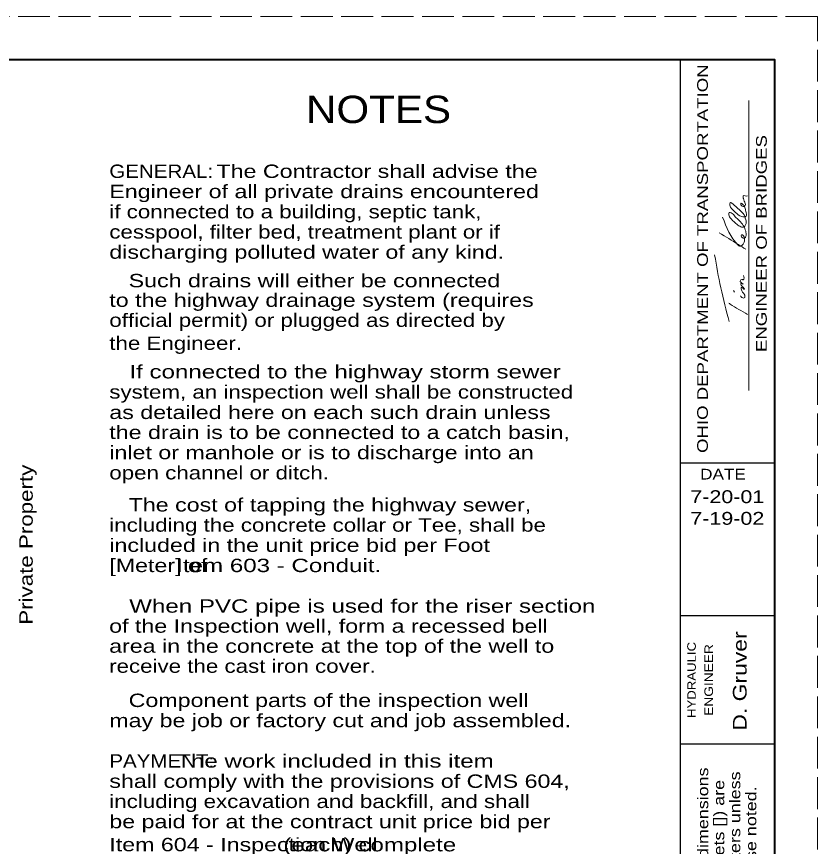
# Model space of a CAD drawing. Extents: x 1083.1 to 1117.1, y 719.4 to 741.4.
# Drawn here: x 1107.77 to 1117.13, y 731.66 to 741.35 of the extents above; entities that cross this region are included whole.
import ezdxf
from ezdxf.enums import TextEntityAlignment as Align

# ---------------------------------------------------------------- set-up
doc = ezdxf.new("R2010")
doc.units = 0
doc.header["$LTSCALE"] = 0.062
doc.linetypes.add('LONG_DASHED', pattern=[7.5, 6, -1.5])
doc.layers.add('1', color=7, linetype='Continuous', lineweight=13)

msp = doc.modelspace()

# ---------------------------------------------------------------- linework, layer by layer
at = {"layer": '1', "lineweight": 25}
for p, q in [((1085.12642, 740.85408), (1116.62642, 740.85408)), ((1115.52642, 719.85408), (1115.52642, 740.85408)), ((1116.62642, 740.85408), (1116.62642, 719.85408)), ((1116.62642, 736.13825), (1115.52642, 736.13825)), ((1116.62642, 734.35408), (1115.52642, 734.35408)), ((1116.62642, 732.85408), (1115.52642, 732.85408))]:
    msp.add_line(p, q, dxfattribs=at)
at = {"layer": '1'}
for p, q in [((1116.32517, 736.98508), (1116.32517, 740.37517)), ((1116.15767, 738.136), (1116.1475, 738.15525))]:
    msp.add_line(p, q, dxfattribs=at)
at = {"layer": '1', "linetype": 'LONG_DASHED'}
msp.add_lwpolyline([(1083.12642, 719.35408), (1117.12642, 719.35408), (1117.12642, 741.35408), (1083.12642, 741.35408)], close=True, dxfattribs=at)
at = {"layer": '1', "lineweight": 40}
msp.add_lwpolyline([(1085.12642, 740.85408), (1116.62642, 740.85408), (1116.62642, 719.85408), (1085.12642, 719.85408)], close=True, dxfattribs=at)
msp.add_lwpolyline([(1085.12642, 740.85408), (1116.62642, 740.85408), (1116.62642, 719.85408), (1085.12642, 719.85408)], close=True, dxfattribs=at)
at = {"layer": '1'}
for points in [[(1116.01825, 739.01108), (1116.20142, 738.68275), (1116.21658, 738.67217), (1116.22675, 738.67217), (1116.25867, 738.69583), (1116.27375, 738.73), (1116.26875, 738.78125), (1116.25183, 738.80308), (1116.23833, 738.80308), (1116.23658, 738.79008), (1116.24675, 738.77492), (1116.26025, 738.7665), (1116.27533, 738.7665), (1116.2905, 738.78808), (1116.29392, 738.80742), (1116.28367, 738.86275), (1116.20142, 738.98317), (1116.15592, 739.02783), (1116.119, 739.06242), (1116.09383, 739.06458), (1116.09558, 739.026), (1116.12075, 738.98725), (1116.188, 738.92492), (1116.23008, 738.8995), (1116.26375, 738.895), (1116.28708, 738.921), (1116.29392, 738.95517), (1116.28883, 738.98092), (1116.25867, 739.05408), (1116.22842, 739.08608), (1116.16783, 739.1395), (1116.13917, 739.16533), (1116.10567, 739.18058), (1116.10225, 739.15258), (1116.11233, 739.12675), (1116.1695, 739.06683), (1116.24017, 739.01958), (1116.29217, 739.02192), (1116.2905, 739.07958), (1116.27867, 739.1225), (1116.26533, 739.14825), (1116.25517, 739.159), (1116.23175, 739.174), (1116.2335, 739.15692), (1116.26875, 739.13542), (1116.28367, 739.14617), (1116.27058, 739.19983), (1116.262, 739.22775), (1116.25867, 739.24042), (1116.25867, 739.25325), (1116.25867, 739.26192), (1116.28367, 739.25975), (1116.30908, 739.25975)], [(1115.97942, 738.82883), (1116.20317, 738.69133), (1116.28883, 738.63567)], [(1116.09567, 737.79183), (1115.997, 738.18708), (1115.92575, 738.56942)], [(1116.22675, 738.09075), (1116.235, 738.08008), (1116.27217, 738.06717), (1116.27692, 738.09958), (1116.25183, 738.136), (1116.23658, 738.17225), (1116.23658, 738.1915), (1116.25183, 738.18525), (1116.262, 738.17442), (1116.27217, 738.17008), (1116.2485, 738.20225), (1116.23658, 738.21725), (1116.2335, 738.23458), (1116.25692, 738.228), (1116.2485, 738.23667), (1116.22333, 738.2645), (1116.2335, 738.27967), (1116.25025, 738.28167), (1116.25867, 738.27967), (1116.26875, 738.301), (1116.262, 738.32892)], [(1116.31083, 737.87625), (1116.10567, 737.99625), (1116.09008, 738.00667)]]:
    msp.add_spline(points, degree=3, dxfattribs=at)

# ---------------------------------------------------------------- texts
for s, height, width, p in [('OHIO DEPARTMENT OF TRANSPORTATION', 0.125, 1.3, (1115.84633, 738.52633)), ('ENGINEER OF BRIDGES', 0.125, 1.3, (1116.53467, 738.70312)), ('Private Property', 0.156, 1.25, (1107.95658, 735.1855)), ('D. Gruver', 0.16, 1.25, (1116.29933, 733.59325)), ('HYDRAULIC', 0.1, 1.15, (1115.7055, 733.60517)), ('ENGINEER', 0.1, 1.2, (1115.90642, 733.60521)), ('All metric dimensions', 0.125, 1.25, (1115.85025, 731.59617)), ('in millimeters unless', 0.125, 1.25, (1116.22525, 731.59621)), ('(in brackets []) are', 0.125, 1.25, (1116.03775, 731.59617)), ('otherwise noted.', 0.125, 1.25, (1116.41275, 731.59617))]:
    msp.add_text(s, height=height, rotation=90, dxfattribs=dict(at, width=width)).set_placement(p, align=Align.CENTER)
for s, height, width, p in [('NOTES', 0.32, 1.15, (1111.15042, 740.11042)), ('GENERAL:', 0.156, 1.15, (1108.85183, 739.46958)), ('   The Contractor shall advise the', 0.156, 1.3, (1109.87783, 739.46958)), ('Engineer of all private drains encountered', 0.156, 1.3, (1108.85183, 739.23358)), ('if connected to a building, septic tank,', 0.156, 1.25, (1108.85183, 738.99758)), ('cesspool, filter bed, treatment plant or if', 0.156, 1.25, (1108.85183, 738.76158)), ('discharging polluted water of any kind.', 0.156, 1.3, (1108.85183, 738.52558)), ('   Such drains will either be connected', 0.156, 1.3, (1108.85183, 738.19242)), ('to the highway drainage system (requires ', 0.156, 1.3, (1108.85183, 737.96367)), ('official permit) or plugged as directed by', 0.156, 1.25, (1108.85183, 737.72967)), ('the Engineer.', 0.156, 1.25, (1108.85183, 737.46125)), ('   If connected to the highway storm sewer', 0.156, 1.35, (1108.85183, 737.12808)), ('system, an inspection well shall be constructed', 0.156, 1.25, (1108.85183, 736.89208)), ('as detailed here on each such drain unless', 0.156, 1.3, (1108.85183, 736.65358)), ('the drain is to be connected to a catch basin,', 0.156, 1.3, (1108.85183, 736.42008)), ('inlet or manhole or is to discharge into an', 0.156, 1.3, (1108.85183, 736.18408)), ('open channel or ditch.', 0.156, 1.25, (1108.85183, 735.94808)), ('   The cost of tapping the highway sewer,', 0.156, 1.3, (1108.85183, 735.57333)), ('including the concrete collar or Tee, shall be', 0.156, 1.25, (1108.85183, 735.33733)), ('included in the unit price bid per Foot', 0.156, 1.3, (1108.85183, 735.10133)), ('[Meter] of', 0.156, 1.3, (1108.85183, 734.86533)), ('          Item 603 - Conduit.', 0.156, 1.35, (1108.85183, 734.86533)), ('   When PVC pipe is used for the riser section ', 0.156, 1.35, (1108.84975, 734.39133)), ('of the Inspection well, form a recessed bell ', 0.156, 1.3, (1108.84975, 734.15733)), ('area in the concrete at the top of the well to ', 0.156, 1.3, (1108.84975, 733.92333)), ('receive the cast iron cover.', 0.156, 1.25, (1108.84975, 733.68933)), ('   Component parts of the inspection well', 0.156, 1.3, (1108.85183, 733.28958)), ('may be job or factory cut and job assembled.', 0.156, 1.3, (1108.85183, 733.05358)), ('PAYMENT:', 0.156, 1.15, (1108.85183, 732.58158)), ('          The work included in this item', 0.156, 1.35, (1108.85183, 732.58158)), ('shall comply with the provisions of CMS 604,', 0.156, 1.3, (1108.85183, 732.34517)), ('including excavation and backfill, and shall', 0.156, 1.25, (1108.85183, 732.10958)), ('be paid for at the contract unit price bid per', 0.156, 1.3, (1108.85183, 731.87358)), ('Item 604 - Inspection Well', 0.156, 1.3, (1108.85183, 731.60467)), ('                          (each) complete', 0.156, 1.35, (1108.85183, 731.60333))]:
    msp.add_text(s, height=height, dxfattribs=dict(at, width=width)).set_placement(p)
for s, height, width, p in [('DATE', 0.125, 1.2, (1116.02312, 735.94683)), ('7-20-01', 0.15, 1.25, (1116.07346, 735.67133)), ('7-19-02', 0.15, 1.25, (1116.07346, 735.41825))]:
    msp.add_text(s, height=height, dxfattribs=dict(at, width=width)).set_placement(p, align=Align.CENTER)

doc.saveas('drawing.dxf')
